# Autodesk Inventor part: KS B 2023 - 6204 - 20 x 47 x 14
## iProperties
IsCustomPart: 0
Created: 2009-02
Part Number: KS B 2023 - 6204 - 20 x 47 x 14
Material: Steel, Mild
Description: 깊은 그루브 볼 베어링
Document SubType Name: Modeling
Standard: KS B 2023
Designer: SeoGD™ [www.esajin.kr]
Standards Organization: KS
Language: ko-KR
Size Designation: 6204 - 20 x 47 x 14
Categories: <MemberInstance><Categories><Category DisplayName="샤프트 부품" InternalName="7f7aeb1f-a693-4053-b835-cee3144e0d98" Mnemonic="SHFT"><Category DisplayName="베어링" Inter
Density: 1 g/cm^3
Author: SeoGD™ [www.esajin.kr]
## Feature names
1. IDS_ARRAYBALL[SIMPL:T] [Circular Pattern]
